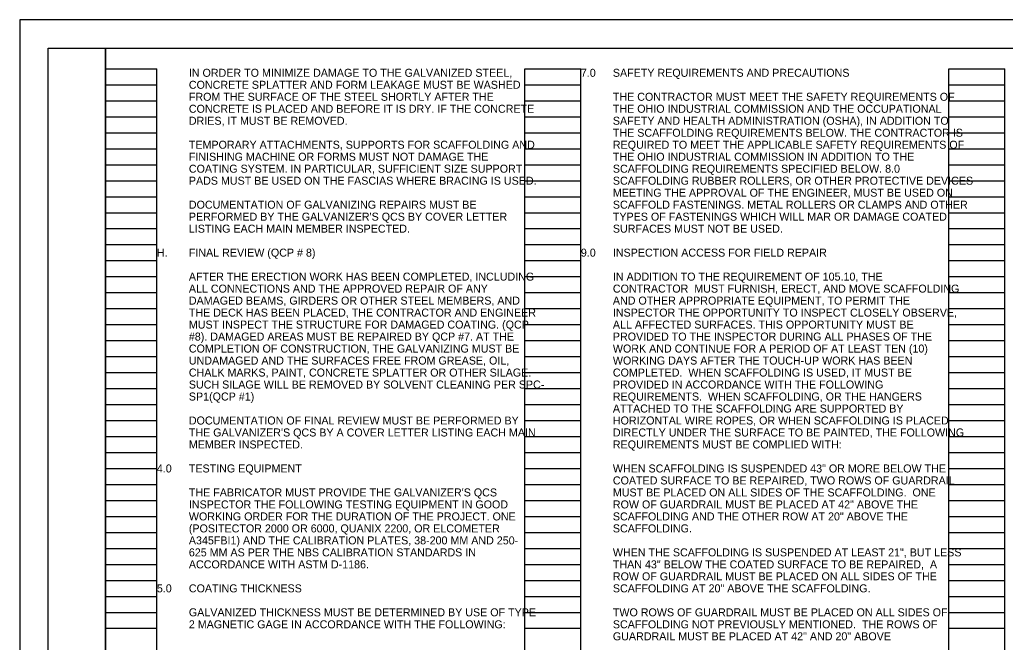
# Model space of a CAD drawing. Extents: x 0 to 34, y 0 to 22.
# Drawn here: x 0 to 17.25, y 11.1 to 22 of the extents above; entities that cross this region are included whole.
import ezdxf

# ---------------------------------------------------------------- set-up
doc = ezdxf.new("R2010")
doc.units = 0
for name, color, linetype in [('BR_P_Gen_Text', 7, 'Continuous'), ('SH_Border', 7, 'Continuous'), ('SH_Cut_Line', 7, 'Continuous'), ('SH_Data', 7, 'Continuous')]:
    doc.layers.add(name, color=color, linetype=linetype)

msp = doc.modelspace()

# ---------------------------------------------------------------- linework, layer by layer
at = {"layer": 'SH_Border'}
for points in [[(0.5, 21.5), (1.5, 21.5), (1.5, 0.5), (0.5, 0.5)], [(1.5, 21.5), (33.5, 21.5), (33.5, 0.5), (1.5, 0.5)]]:
    msp.add_lwpolyline(points, close=True, dxfattribs=at)
at = {"layer": 'SH_Cut_Line'}
msp.add_lwpolyline([(0, 0), (34, 0), (34, 22), (0, 22)], close=True, dxfattribs=at)
at = {"layer": 'SH_Data'}
for p, q in [((1.5, 0.98), (1.5, 21.14)), ((1.5, 21.14), (2.4, 21.14)), ((2.4, 0.98), (2.4, 21.14)), ((8.84, 0.98), (8.84, 21.14)), ((8.84, 21.14), (9.82, 21.14)), ((9.82, 0.98), (9.82, 21.14)), ((16.26, 0.98), (16.26, 21.14)), ((16.26, 21.14), (17.24, 21.14)), ((17.24, 0.98), (17.24, 21.14)), ((1.5, 20.86), (2.4, 20.86)), ((8.84, 20.86), (9.82, 20.86)), ((16.26, 20.86), (17.24, 20.86)), ((1.5, 20.58), (2.4, 20.58)), ((8.84, 20.58), (9.82, 20.58)), ((16.26, 20.58), (17.24, 20.58)), ((1.5, 20.3), (2.4, 20.3)), ((8.84, 20.3), (9.82, 20.3)), ((16.26, 20.3), (17.24, 20.3)), ((1.5, 20.02), (2.4, 20.02)), ((8.84, 20.02), (9.82, 20.02)), ((16.26, 20.02), (17.24, 20.02)), ((1.5, 19.74), (2.4, 19.74)), ((8.84, 19.74), (9.82, 19.74)), ((16.26, 19.74), (17.24, 19.74)), ((1.5, 19.46), (2.4, 19.46)), ((8.84, 19.46), (9.82, 19.46)), ((16.26, 19.46), (17.24, 19.46)), ((1.5, 19.18), (2.4, 19.18)), ((8.84, 19.18), (9.82, 19.18)), ((16.26, 19.18), (17.24, 19.18)), ((1.5, 18.9), (2.4, 18.9)), ((8.84, 18.9), (9.82, 18.9)), ((16.26, 18.9), (17.24, 18.9)), ((1.5, 18.62), (2.4, 18.62)), ((8.84, 18.62), (9.82, 18.62)), ((16.26, 18.62), (17.24, 18.62)), ((1.5, 18.34), (2.4, 18.34)), ((8.84, 18.34), (9.82, 18.34)), ((16.26, 18.34), (17.24, 18.34)), ((1.5, 18.06), (2.4, 18.06)), ((8.84, 18.06), (9.82, 18.06)), ((16.26, 18.06), (17.24, 18.06)), ((1.5, 17.78), (2.4, 17.78)), ((8.84, 17.78), (9.82, 17.78)), ((16.26, 17.78), (17.24, 17.78)), ((1.5, 17.5), (2.4, 17.5)), ((8.84, 17.5), (9.82, 17.5)), ((16.26, 17.5), (17.24, 17.5)), ((1.5, 17.22), (2.4, 17.22)), ((8.84, 17.22), (9.82, 17.22)), ((16.26, 17.22), (17.24, 17.22)), ((1.5, 16.94), (2.4, 16.94)), ((8.84, 16.94), (9.82, 16.94)), ((16.26, 16.94), (17.24, 16.94)), ((1.5, 16.66), (2.4, 16.66)), ((8.84, 16.66), (9.82, 16.66)), ((16.26, 16.66), (17.24, 16.66)), ((1.5, 16.38), (2.4, 16.38)), ((8.84, 16.38), (9.82, 16.38)), ((16.26, 16.38), (17.24, 16.38)), ((1.5, 16.1), (2.4, 16.1)), ((8.84, 16.1), (9.82, 16.1)), ((16.26, 16.1), (17.24, 16.1)), ((1.5, 15.82), (2.4, 15.82)), ((8.84, 15.82), (9.82, 15.82)), ((16.26, 15.82), (17.24, 15.82)), ((1.5, 15.54), (2.4, 15.54)), ((8.84, 15.54), (9.82, 15.54)), ((16.26, 15.54), (17.24, 15.54)), ((1.5, 15.26), (2.4, 15.26)), ((8.84, 15.26), (9.82, 15.26)), ((16.26, 15.26), (17.24, 15.26)), ((1.5, 14.98), (2.4, 14.98)), ((8.84, 14.98), (9.82, 14.98)), ((16.26, 14.98), (17.24, 14.98)), ((1.5, 14.7), (2.4, 14.7)), ((8.84, 14.7), (9.82, 14.7)), ((16.26, 14.7), (17.24, 14.7)), ((1.5, 14.42), (2.4, 14.42)), ((8.84, 14.42), (9.82, 14.42)), ((16.26, 14.42), (17.24, 14.42)), ((1.5, 14.14), (2.4, 14.14)), ((8.84, 14.14), (9.82, 14.14)), ((16.26, 14.14), (17.24, 14.14)), ((1.5, 13.86), (2.4, 13.86)), ((8.84, 13.86), (9.82, 13.86)), ((16.26, 13.86), (17.24, 13.86)), ((1.5, 13.58), (2.4, 13.58)), ((8.84, 13.58), (9.82, 13.58)), ((16.26, 13.58), (17.24, 13.58)), ((1.5, 13.3), (2.4, 13.3)), ((8.84, 13.3), (9.82, 13.3)), ((16.26, 13.3), (17.24, 13.3)), ((1.5, 13.02), (2.4, 13.02)), ((8.84, 13.02), (9.82, 13.02)), ((16.26, 13.02), (17.24, 13.02)), ((1.5, 12.74), (2.4, 12.74)), ((8.84, 12.74), (9.82, 12.74)), ((16.26, 12.74), (17.24, 12.74)), ((1.5, 12.46), (2.4, 12.46)), ((8.84, 12.46), (9.82, 12.46)), ((16.26, 12.46), (17.24, 12.46)), ((1.5, 12.18), (2.4, 12.18)), ((8.84, 12.18), (9.82, 12.18)), ((16.26, 12.18), (17.24, 12.18)), ((1.5, 11.9), (2.4, 11.9)), ((8.84, 11.9), (9.82, 11.9)), ((16.26, 11.9), (17.24, 11.9)), ((1.5, 11.62), (2.4, 11.62)), ((8.84, 11.62), (9.82, 11.62)), ((16.26, 11.62), (17.24, 11.62)), ((1.5, 11.34), (2.4, 11.34)), ((8.84, 11.34), (9.82, 11.34)), ((16.26, 11.34), (17.24, 11.34))]:
    msp.add_line(p, q, dxfattribs=at)

# ---------------------------------------------------------------- texts
at = {"layer": 'BR_P_Gen_Text'}
for s, p in [('IN ORDER TO MINIMIZE DAMAGE TO THE GALVANIZED STEEL, ', (2.96, 21)), ('7.0 ', (9.82, 21)), ('SAFETY REQUIREMENTS AND PRECAUTIONS', (10.38, 21)), ('CONCRETE SPLATTER AND FORM LEAKAGE MUST BE WASHED ', (2.96, 20.79)), ('FROM THE SURFACE OF THE STEEL SHORTLY AFTER THE ', (2.96, 20.58)), ('THE CONTRACTOR MUST MEET THE SAFETY REQUIREMENTS OF ', (10.38, 20.58)), ('CONCRETE IS PLACED AND BEFORE IT IS DRY. IF THE CONCRETE ', (2.96, 20.37)), ('THE OHIO INDUSTRIAL COMMISSION AND THE OCCUPATIONAL ', (10.38, 20.37)), ('DRIES, IT MUST BE REMOVED.', (2.96, 20.16)), ('SAFETY AND HEALTH ADMINISTRATION (OSHA), IN ADDITION TO ', (10.38, 20.16)), ('THE SCAFFOLDING REQUIREMENTS BELOW. THE CONTRACTOR IS ', (10.38, 19.95)), ('TEMPORARY ATTACHMENTS, SUPPORTS FOR SCAFFOLDING AND ', (2.96, 19.74)), ('REQUIRED TO MEET THE APPLICABLE SAFETY REQUIREMENTS OF ', (10.38, 19.74)), ('FINISHING MACHINE OR FORMS MUST NOT DAMAGE THE ', (2.96, 19.53)), ('THE OHIO INDUSTRIAL COMMISSION IN ADDITION TO THE ', (10.38, 19.53)), ('COATING SYSTEM. IN PARTICULAR, SUFFICIENT SIZE SUPPORT ', (2.96, 19.32)), ('SCAFFOLDING REQUIREMENTS SPECIFIED BELOW. 8.0 ', (10.38, 19.32)), ('PADS MUST BE USED ON THE FASCIAS WHERE BRACING IS USED. ', (2.96, 19.11)), ('SCAFFOLDING RUBBER ROLLERS, OR OTHER PROTECTIVE DEVICES ', (10.38, 19.11)), ('MEETING THE APPROVAL OF THE ENGINEER, MUST BE USED ON ', (10.38, 18.9)), ('DOCUMENTATION OF GALVANIZING REPAIRS MUST BE ', (2.96, 18.69)), ('SCAFFOLD FASTENINGS. METAL ROLLERS OR CLAMPS AND OTHER ', (10.38, 18.69)), ("PERFORMED BY THE GALVANIZER'S QCS BY COVER LETTER ", (2.96, 18.48)), ('TYPES OF FASTENINGS WHICH WILL MAR OR DAMAGE COATED ', (10.38, 18.48)), ('LISTING EACH MAIN MEMBER INSPECTED.', (2.96, 18.27)), ('SURFACES MUST NOT BE USED.', (10.38, 18.27)), ('H. ', (2.4, 17.85)), ('FINAL REVIEW (QCP # 8)', (2.96, 17.85)), ('9.0', (9.82, 17.85)), ('INSPECTION ACCESS FOR FIELD REPAIR', (10.38, 17.85)), ('AFTER THE ERECTION WORK HAS BEEN COMPLETED, INCLUDING ', (2.96, 17.43)), ('IN ADDITION TO THE REQUIREMENT OF 105.10, THE  ', (10.38, 17.43)), ('ALL CONNECTIONS AND THE APPROVED REPAIR OF ANY ', (2.96, 17.22)), ('CONTRACTOR  MUST FURNISH, ERECT, AND MOVE SCAFFOLDING ', (10.38, 17.22)), ('DAMAGED BEAMS, GIRDERS OR OTHER STEEL MEMBERS, AND ', (2.96, 17.01)), ('AND OTHER APPROPRIATE EQUIPMENT, TO PERMIT THE ', (10.38, 17.01)), ('THE DECK HAS BEEN PLACED, THE CONTRACTOR AND ENGINEER ', (2.96, 16.8)), ('INSPECTOR THE OPPORTUNITY TO INSPECT CLOSELY OBSERVE, ', (10.38, 16.8)), ('MUST INSPECT THE STRUCTURE FOR DAMAGED COATING. (QCP ', (2.96, 16.59)), ('ALL AFFECTED SURFACES. THIS OPPORTUNITY MUST BE ', (10.38, 16.59)), ('#8). DAMAGED AREAS MUST BE REPAIRED BY QCP #7. AT THE ', (2.96, 16.38)), ('PROVIDED TO THE INSPECTOR DURING ALL PHASES OF THE ', (10.38, 16.38)), ('COMPLETION OF CONSTRUCTION, THE GALVANIZING MUST BE ', (2.96, 16.17)), ('WORK AND CONTINUE FOR A PERIOD OF AT LEAST TEN (10) ', (10.38, 16.17)), ('UNDAMAGED AND THE SURFACES FREE FROM GREASE, OIL, ', (2.96, 15.96)), ('WORKING DAYS AFTER THE TOUCH-UP WORK HAS BEEN ', (10.38, 15.96)), ('CHALK MARKS, PAINT, CONCRETE SPLATTER OR OTHER SILAGE. ', (2.96, 15.75)), ('COMPLETED.  WHEN SCAFFOLDING IS USED, IT MUST BE ', (10.38, 15.75)), ('SUCH SILAGE WILL BE REMOVED BY SOLVENT CLEANING PER SPC-', (2.96, 15.54)), ('PROVIDED IN ACCORDANCE WITH THE FOLLOWING ', (10.38, 15.54)), ('SP1(QCP #1)', (2.96, 15.33)), ('REQUIREMENTS.  WHEN SCAFFOLDING, OR THE HANGERS ', (10.38, 15.33)), ('ATTACHED TO THE SCAFFOLDING ARE SUPPORTED BY ', (10.38, 15.12)), ('DOCUMENTATION OF FINAL REVIEW MUST BE PERFORMED BY ', (2.96, 14.91)), ('HORIZONTAL WIRE ROPES, OR WHEN SCAFFOLDING IS PLACED ', (10.38, 14.91)), ("THE GALVANIZER'S QCS BY A COVER LETTER LISTING EACH MAIN ", (2.96, 14.7)), ('DIRECTLY UNDER THE SURFACE TO BE PAINTED, THE FOLLOWING ', (10.38, 14.7)), ('MEMBER INSPECTED.', (2.96, 14.49)), ('REQUIREMENTS MUST BE COMPLIED WITH:', (10.38, 14.49)), ('4.0 ', (2.4, 14.07)), ('TESTING EQUIPMENT', (2.96, 14.07)), ('WHEN SCAFFOLDING IS SUSPENDED 43" OR MORE BELOW THE ', (10.38, 14.07)), ('COATED SURFACE TO BE REPAIRED, TWO ROWS OF GUARDRAIL ', (10.38, 13.86)), ("THE FABRICATOR MUST PROVIDE THE GALVANIZER'S QCS ", (2.96, 13.65)), ('MUST BE PLACED ON ALL SIDES OF THE SCAFFOLDING.  ONE ', (10.38, 13.65)), ('INSPECTOR THE FOLLOWING TESTING EQUIPMENT IN GOOD ', (2.96, 13.44)), ('ROW OF GUARDRAIL MUST BE PLACED AT 42" ABOVE THE ', (10.38, 13.44)), ('WORKING ORDER FOR THE DURATION OF THE PROJECT. ONE ', (2.96, 13.23)), ('SCAFFOLDING AND THE OTHER ROW AT 20" ABOVE THE ', (10.38, 13.23)), ('(POSITECTOR 2000 OR 6000, QUANIX 2200, OR ELCOMETER ', (2.96, 13.02)), ('SCAFFOLDING.', (10.38, 13.02)), ('A345FBI1) AND THE CALIBRATION PLATES, 38-200 MM AND 250-', (2.96, 12.81)), ('625 MM AS PER THE NBS CALIBRATION STANDARDS IN ', (2.96, 12.6)), ('WHEN THE SCAFFOLDING IS SUSPENDED AT LEAST 21", BUT LESS  ', (10.38, 12.6)), ('ACCORDANCE WITH ASTM D-1186.', (2.96, 12.39)), ('THAN 43" BELOW THE COATED SURFACE TO BE REPAIRED,  A ', (10.38, 12.39)), ('ROW OF GUARDRAIL MUST BE PLACED ON ALL SIDES OF THE ', (10.38, 12.18)), ('5.0 ', (2.4, 11.97)), ('COATING THICKNESS', (2.96, 11.97)), ('SCAFFOLDING AT 20" ABOVE THE SCAFFOLDING.', (10.38, 11.97)), ('GALVANIZED THICKNESS MUST BE DETERMINED BY USE OF TYPE ', (2.96, 11.55)), ('TWO ROWS OF GUARDRAIL MUST BE PLACED ON ALL SIDES OF ', (10.38, 11.55)), ('2 MAGNETIC GAGE IN ACCORDANCE WITH THE FOLLOWING:', (2.96, 11.34)), ('SCAFFOLDING NOT PREVIOUSLY MENTIONED.  THE ROWS OF ', (10.38, 11.34)), ('GUARDRAIL MUST BE PLACED AT 42" AND 20" ABOVE ', (10.38, 11.13))]:
    msp.add_text(s, height=0.14, dxfattribs=at).set_placement(p)

doc.saveas('drawing.dxf')
